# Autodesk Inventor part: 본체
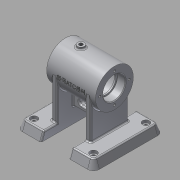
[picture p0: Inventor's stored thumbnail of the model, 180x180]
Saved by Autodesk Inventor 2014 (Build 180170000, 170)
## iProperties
Created: 2016-07
Part Number: 본체
Material: 알루미늄 6061
Document SubType Name: Modeling
Designer: SCD-A13
Density: 2.71 g/cm^3
Appearance: 알루미늄 - 평지
Mass: 509.63 g
Surface Area: 545.772 cm^2
Volume: 188.055 cm^3
Author: SCD-A13
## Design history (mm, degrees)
sketch "스케치1"
  geometry: L1 (-55, -50)-(-20, -50); L2 (-20, -50)-(-20, 50); L3 (-20, 50)-(-55, 50); L4 (-55, 50)-(-55, -50); L5 (-55, -50)-(-20, 50); L6 (-20, -50)-(-55, 50); 3 further points
  constraints: 12 end point, 3 midpoint, 2 parallel, 1 horizontal, 1 horizontal alignment, 1 perpendicular
  dimensions: "d0" = 100 distance of L1.end L2.end; "d1" = 35 distance of L2.end L3.end; "d2" = 55 distance from line of point (0, 0) L4
extrude "돌출1" new body sketch "스케치1" distance "d3" = 12; taper "d4" = 0 deg
node "작업 평면1"
sketch "스케치2"
  geometry: L1 (-20, -50)-(-20, 50) reference; L2 (-28, -27)-(-20, -27); L3 (-20, -27)-(-20, 27); L4 (-20, 27)-(-28, 27); L5 (-28, 27)-(-28, -27); L6 (-28, -27)-(-20, 27); L7 (-20, -27)-(-28, 27); 5 further points
  constraints: 12 end point, 3 midpoint, 2 parallel, 1 horizontal, 1 horizontal alignment, 1 perpendicular, 1 point on line
  dimensions: "d12" = 8 distance of L3.end L4.end; "d13" = 54 distance of L4.end L2.start
extrude "돌출2" join sketch "스케치2" distance "d14" = 58; taper "d15" = 0 deg
sketch "스케치3"
  geometry: C1 r 27 at (0, 70); 1 further point
  constraints: 1 centre point, 1 vertical alignment
  dimensions: "d16" = 54 diameter of C1; "d17" = 70 distance of point (0, 0) C1.centre
extrude "돌출3" join sketch "스케치3" stored distance "d18" = 70; taper "d19" = 0 deg
sketch "스케치9"
  geometry: C1 r 16 at (0, 0) reference; 2 further points
  constraints: 1 horizontal alignment
  dimensions: "d37" = 21 distance of point (-21, 0) C1.centre
hole "구멍1" sketch "스케치9" at (-21, 0) diameter "d38" = 3.242; stored, may be unused: countersink angle "d42" = 90 deg, drill point angle "d44" = 118 deg; dims "d39" = 8, "d40" = 4, "d41" = 2, "d43" = 10
node "작업 평면2"
sketch "스케치10"
  geometry: L1 (-35, 27)-(-35, -27) reference; C1 r 5 at (-13, 0); 1 further point
  constraints: 1 centre point, 1 horizontal alignment
  dimensions: "d49" = 22 distance from line of C1.centre L1; "d50" = 10 diameter of C1
extrude "돌출9" join sketch "스케치10" stored distance "d51" = 42; taper "d52" = 0 deg
fillet "모깎기8" dims "d53" = 2
node "작업 평면4"
  node "작업 평면3"
sketch "스케치11"
  geometry: L1 (-35, 27)-(-35, -27) reference; C1 r 6 at (0, 0); 2 further points
  constraints: 1 centre point, 1 horizontal alignment, 1 midpoint, 1 vertical alignment
  dimensions: "d65" = 12 diameter of C1
extrude "돌출10" join sketch "스케치11" stored distance "d66" = 42; taper "d67" = 0 deg
fillet "모깎기9" dims "d68" = 2
sketch "스케치12"
  geometry: L1 (-35, 50.621)-(-35, 89.379) reference; L2 (-35, 89.379)-(-25, 89.379) reference; L3 (-25, 89.379)-(-24.026, 91) reference; L4 (-24.026, 91)-(-25, 92.621) reference; L5 (-25, 92.621)-(-35, 92.621) reference; L6 (-35, 92.621)-(-35, 97) reference; L7 (-35, 97)-(6, 97) reference; L8 (8, 99)-(8, 100) reference; L9 (8, 100)-(18, 100) reference; L10 (18, 100)-(18, 99) reference; L11 (20, 97)-(35, 97) reference; L12 (35, 97)-(35, 92.621) reference; L13 (35, 92.621)-(25, 92.621) reference; L14 (25, 92.621)-(24.026, 91) reference; L15 (24.026, 91)-(25, 89.379) reference; L16 (25, 89.379)-(35, 89.379) reference; L17 (35, 89.379)-(35, 50.621) reference; L18 (35, 50.621)-(25, 50.621) reference; L19 (25, 50.621)-(24.026, 49) reference; L20 (24.026, 49)-(25, 47.379) reference; L21 (25, 47.379)-(35, 47.379) reference; L22 (35, 47.379)-(35, 43) reference; L23 (35, 43)-(28, 43) reference; L24 (28, 43)-(28, 12) reference; L25 (28, 12)-(55, 12) reference; L26 (55, 12)-(55, 0) reference; L27 (55, 0)-(20, 0) reference; L28 (20, 0)-(20, 43) reference; L29 (20, 43)-(-35, 43) reference; L30 (-35, 43)-(-35, 47.379) reference; L31 (-35, 47.379)-(-25, 47.379) reference; L32 (-25, 47.379)-(-24.026, 49) reference; L33 (-24.026, 49)-(-25, 50.621) reference; L34 (-25, 50.621)-(-35, 50.621) reference; L35 (20, 22)-(-20, 22); L36 (-20, 22)-(-20, 48); L37 (-20, 48)-(20, 48); L38 (20, 48)-(20, 22); 3 further points
  constraints: 8 end point, 2 parallel, 2 point on line, 1 horizontal, 1 midpoint, 1 perpendicular, 2 other
  dimensions: "d78" = 21 distance between parallel lines of L35 L29
extrude "돌출11" join sketch "스케치12" stored distance "d79" = 8; taper "d80" = 0 deg
sketch "스케치13"
  geometry: L1 (-20, 43.298)-(20, 43.298) reference; L2 (-8, 32)-(8, 32); L3 (-8, 28.5)-(8, 28.5); L4 (8, 35.5)-(-8, 35.5); A1 r 3.5 centre (-8, 32) between (-8, 35.5) and (-8, 28.5); A2 r 3.5 centre (8, 32) between (8, 28.5) and (8, 35.5); 2 further points
  constraints: 8 end point, 4 point on circle, 4 tangent, 2 centre point, 2 parallel, 1 midpoint, 1 vertical alignment
  dimensions: "d81" = 23 dimension on A2 A1; "d82" = 32 distance of point (0, 0) point (0, 32); "d84" = 3.5 radius of A1
extrude "돌출12" cut sketch "스케치13" stored distance "d85" = 8; taper "d86" = 0 deg
sketch "스케치14"
  geometry: L1 (-55, -50)-(-20, -50) reference; L2 (-55, 50)-(-55, -50) reference; 6 further points
  dimensions: "d93" = 12.5 distance from line of L1 point (-42.5, -37.5); "d94" = 12.5 distance from line of L2 point (-42.5, -37.5)
hole "구멍4" sketch "스케치14" at (-42.5, -37.5) diameter "d95" = 6; stored, may be unused: countersink angle "d99" = 90 deg, drill point angle "d101" = 118 deg; dims "d96" = 8, "d97" = 10, "d98" = 4, "d100" = 10
sketch "스케치19"
  geometry: 1 further point
feature "면 기울기2" dims angle "d116" = 20 deg
fillet "모깎기17" dims "d117" = 10, "d118" = 5
fillet "모깎기18" dims "d119" = 10, "d120" = 5
fillet "모깎기19" dims "d121" = 2
fillet "모깎기20" dims "d122" = 2
feature "면 기울기3" dims angle "d123" = 20 deg
fillet "모깎기21" dims "d124" = 10, "d125" = 5
fillet "모깎기22" dims "d126" = 10, "d127" = 5
fillet "모깎기23" dims "d128" = 2
fillet "모깎기24" dims "d129" = 2
fillet "모깎기25" dims "d130" = 2
fillet "모깎기26" dims "d131" = 2
fillet "모깎기27" dims "d132" = 2
fillet "모깎기28" dims "d133" = 2
fillet "모깎기29" dims "d134" = 2
node "작업 평면7"
sketch "스케치20"
  geometry: L1 (-20.739, 2.9)-(20.739, 2.9); L2 (20.739, 2.9)-(20.739, -2.9); L3 (20.739, -2.9)-(-20.739, -2.9); L4 (-20.739, -2.9)-(-20.739, 2.9); L5 (-35, 27)-(35, 27) reference; 3 further points
  constraints: 2 midpoint, 1 vertical alignment, 2 other
  dimensions: "d135" = 27 distance from line of point (20.739, 0) L5
feature "엠보싱2" sketch "스케치20" dims "d136" = 0.5, "d137" = 0
sketch "스케치21"
  geometry: C1 r 27 at (0, 0) reference; C2 r 16 at (0, 0); 1 further point
  constraints: 1 centre point, 1 coincident
  dimensions: "d138" = 32 diameter of C2
extrude "돌출14" cut sketch "스케치21" distance "d139" = 12; taper "d140" = 0 deg
sketch "스케치22"
  geometry: C1 r 27 at (0, 0) reference; C2 r 16 at (0, 0); 1 further point
  constraints: 1 centre point, 1 coincident
  dimensions: "d141" = 32 diameter of C2
extrude "돌출15" cut sketch "스케치22" distance "d142" = 12; taper "d143" = 0 deg
sketch "스케치23"
  geometry: C1 r 16 at (0, 0) reference; C2 r 14 at (0, 0); 1 further point
  constraints: 1 centre point, 1 coincident
  dimensions: "d144" = 28 diameter of C2
extrude "돌출16" cut sketch "스케치23" distance "d145" = 2; taper "d146" = 0 deg
sketch "스케치24"
  geometry: C1 r 16 at (0, 0) reference; C2 r 14 at (0, 0); 1 further point
  constraints: 1 centre point, 1 coincident
  dimensions: "d147" = 28 diameter of C2
extrude "돌출17" cut sketch "스케치24" distance "d148" = 2; taper "d149" = 0 deg
sketch "스케치25"
  geometry: C1 r 14 at (0, 0) reference; C2 r 22 at (0, 0); 1 further point
  constraints: 1 centre point, 1 coincident
  dimensions: "d150" = 44 diameter of C2
extrude "돌출18" cut sketch "스케치25" distance "d151" = 42; taper "d152" = 0 deg
fillet "모깎기30" dims "d153" = 3
fillet "모깎기31" dims "d154" = 0.3
hole "구멍5" diameter "d157" = 5.188; stored, may be unused: countersink angle "d161" = 90 deg, drill point angle "d163" = 118 deg; dims "d155" = 10, "d156" = 10, "d158" = 8, "d159" = 10, "d160" = 4, "d162" = 10
hole "구멍6" diameter "d166" = 5.188; stored, may be unused: countersink angle "d170" = 90 deg, drill point angle "d172" = 118 deg; dims "d164" = 10, "d165" = 10, "d167" = 8, "d168" = 10, "d169" = 4, "d171" = 10
chamfer "모따기1" distance "d173" = 1; stored, may be unused: second distance "d174" = 2, angle "d175" = 45 deg
node "솔리드1"
pattern_circular "원형 패턴1" dims angle "d46" = 360 deg
mirror "대칭2"
mirror "대칭3"
mirror "대칭5"
mirror "대칭6"
node "작업축1"
node "절단 모서리 투영1"
other parameters: "d7" = 0, "d63" = 32 deg
